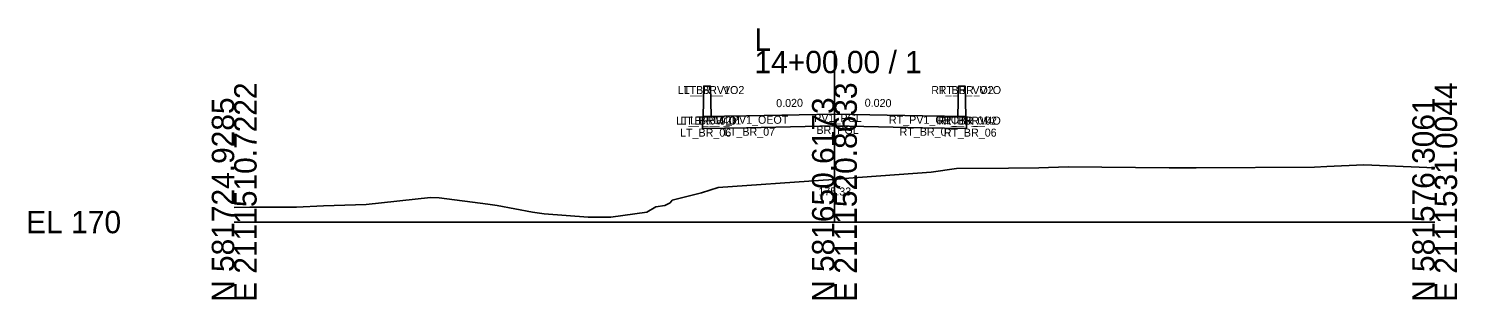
# Model space of a CAD drawing. Extents: x -486 to 1153, y -333 to 9539.
# Drawn here: x -25.7 to 152.8, y 3990.3 to 4024.2 of the extents above; entities that cross this region are included whole.
import ezdxf

# ---------------------------------------------------------------- set-up
doc = ezdxf.new("R2010")
doc.units = 0
for name, color, linetype in [('Default', 7, 'Continuous'), ('Exist Cross Section Cell', 7, 'Continuous'), ('Exist XS Ground Line', 7, 'Continuous'), ('Prop CMT Concrete Structures', 7, 'Continuous'), ('Prop XS SE Text', 7, 'Continuous'), ('Scratch_Level_0', 7, 'Continuous')]:
    doc.layers.add(name, color=color, linetype=linetype)

msp = doc.modelspace()

# ---------------------------------------------------------------- linework, layer by layer
at = {"layer": 'Exist Cross Section Cell'}
for p, q in [((75, 4000), (75, 4021.44)), ((0, 4000), (75, 4000)), ((75, 4000), (150, 4000))]:
    msp.add_line(p, q, dxfattribs=at)
at = {"layer": 'Exist XS Ground Line'}
for p, q in [((87.1, 4006.26), (90.25, 4006.72)), ((90.25, 4006.72), (96.75, 4006.77)), ((96.75, 4006.77), (100.54, 4006.78)), ((100.54, 4006.78), (104.21, 4006.93)), ((104.21, 4006.93), (116.83, 4006.8)), ((116.83, 4006.8), (120.2, 4006.8)), ((120.2, 4006.8), (134.97, 4006.88)), ((134.97, 4006.88), (136.51, 4006.94)), ((136.51, 4006.94), (141.16, 4007.15)), ((141.16, 4007.15), (150, 4006.81)), ((60.48, 4004.33), (73.61, 4005.25)), ((73.61, 4005.25), (75, 4005.33)), ((75, 4005.33), (75.81, 4005.41)), ((75.81, 4005.41), (76.23, 4005.47)), ((76.23, 4005.47), (87.1, 4006.26)), ((16.48, 4002.18), (24.51, 4003.06)), ((24.51, 4003.06), (25.63, 4003.02)), ((25.63, 4003.02), (31.67, 4002.23)), ((54.48, 4002.42), (54.72, 4002.73)), ((54.72, 4002.73), (56.55, 4003.19)), ((56.55, 4003.19), (58.37, 4003.66)), ((58.37, 4003.66), (60.48, 4004.33)), ((0, 4001.84), (1.97, 4001.85)), ((1.97, 4001.85), (7.77, 4001.85)), ((7.77, 4001.85), (11.16, 4002.02)), ((11.16, 4002.02), (16.48, 4002.18)), ((31.67, 4002.23), (32.85, 4002.07)), ((32.85, 4002.07), (37.29, 4001.24)), ((37.29, 4001.24), (38.72, 4001.04)), ((38.72, 4001.04), (44.22, 4000.61)), ((47.04, 4000.63), (51.57, 4001.23)), ((51.57, 4001.23), (52.7, 4001.89)), ((52.7, 4001.89), (53.8, 4002.09)), ((53.8, 4002.09), (54.48, 4002.42)), ((44.22, 4000.61), (47.04, 4000.63))]:
    msp.add_line(p, q, dxfattribs=at)
at = {"layer": 'Prop CMT Concrete Structures'}
for points in [[(59.58, 4013.22), (59.5, 4017.03), (58.67, 4017.03), (58.58, 4013.2)], [(90.42, 4013.22), (90.5, 4017.03), (91.33, 4017.03), (91.42, 4013.2)], [(75, 4013.53), (64, 4013.31), (58.5, 4013.2)], [(75, 4012.03), (75, 4013.53)], [(75, 4013.53), (86, 4013.31), (91.5, 4013.2)], [(75, 4012.03), (75, 4013.53)], [(58.5, 4013.2), (58.5, 4011.7)], [(58.5, 4011.7), (64, 4011.81), (75, 4012.03)], [(58.58, 4013.2), (59.58, 4013.22)], [(91.5, 4011.7), (86, 4011.81), (75, 4012.03)], [(91.42, 4013.2), (90.42, 4013.22)], [(91.5, 4013.2), (91.5, 4011.7)]]:
    msp.add_lwpolyline(points, dxfattribs=at)

# ---------------------------------------------------------------- texts
at = {"layer": 'Default'}
for s, height, p in [('175.33', 1, (73, 4003.33)), ('-', 0.0001, (0, 4000))]:
    msp.add_text(s, height=height, dxfattribs=at).set_placement(p)
at = {"layer": 'Exist Cross Section Cell'}
for s, p in [('L', (65, 4021.44)), ('14+00.00 / 1', (65, 4018.64)), ('EL 170', (-26, 3998.6))]:
    msp.add_text(s, height=2.8, dxfattribs=at).set_placement(p)
for s, p in [('E 2111510.7222', (2.8, 3990)), ('E 2111520.8633', (77.8, 3990)), ('E 2111531.0044', (152.8, 3990)), ('N 581724.9285', (0, 3990)), ('N 581650.6173', (75, 3990)), ('N 581576.3061', (150, 3990))]:
    msp.add_text(s, height=2.8, rotation=90, dxfattribs=at).set_placement(p)
at = {"layer": 'Prop XS SE Text'}
for rotation, p in [(1.1458, (67.73, 4014.38)), (358.8542, (78.77, 4014.45))]:
    msp.add_text('0.020', height=1, rotation=rotation, dxfattribs=at).set_placement(p)
at = {"layer": 'Scratch_Level_0'}
for s, p in [('LT_BR_V1O', (55.41, 4016.03)), ('LT_BR_VO2', (56.16, 4016.03)), ('RT_BR_VO2', (87.1, 4016.03)), ('RT_BR_V1O', (88.02, 4016.03)), ('PV1_PGL', (72.47, 4012.53)), ('LT_BR_V4O', (55.21, 4012.2)), ('LT_BR_06', (55.71, 4010.7)), ('LT_BR_02', (55.74, 4012.2)), ('LT_BR_01', (56.97, 4012.22)), ('LT_PV1_OEOT', (59.87, 4012.31)), ('LT_BR_07', (61.19, 4010.81)), ('BR_PGL', (72.75, 4011.03)), ('RT_PV1_OEOT', (81.81, 4012.31)), ('RT_BR_07', (83.14, 4010.81)), ('RT_BR_01', (87.74, 4012.22)), ('RT_BR_V4O', (87.98, 4012.2)), ('RT_BR_06', (88.65, 4010.7)), ('RT_BR_02', (88.68, 4012.2))]:
    msp.add_text(s, height=1, dxfattribs=at).set_placement(p)

doc.saveas('drawing.dxf')
